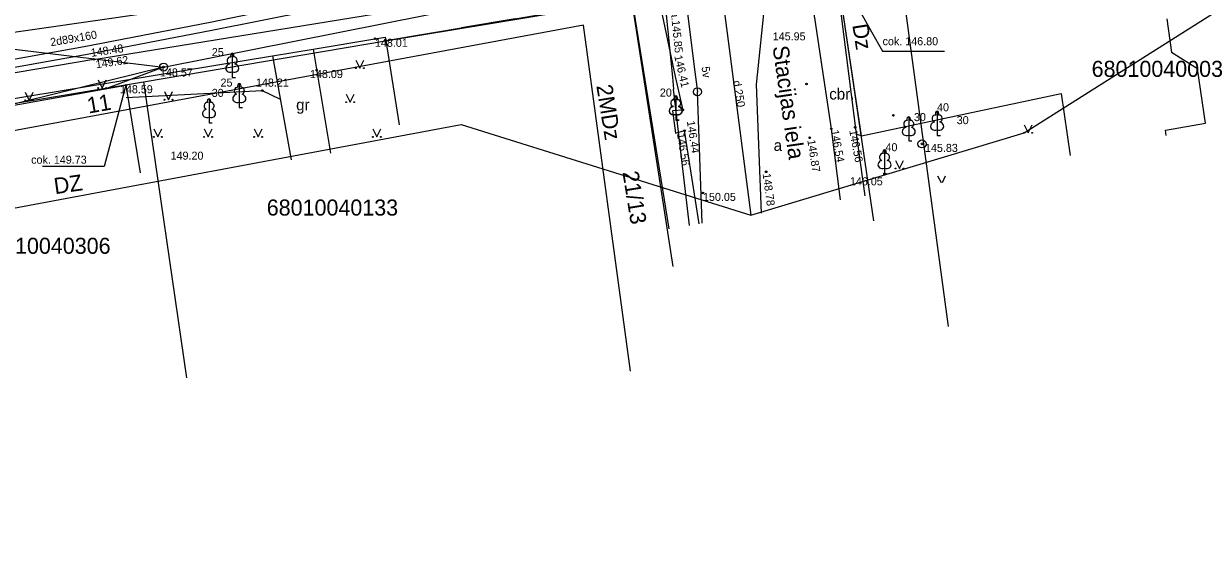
# Model space of a CAD drawing. Extents: x 728492 to 729038, y 272968 to 273171.
# Drawn here: x 728626.4 to 728700.1, y 273032.9 to 273065.2 of the extents above; entities that cross this region are included whole.
import ezdxf

# ---------------------------------------------------------------- set-up
doc = ezdxf.new("R2010")
doc.units = 0
for name, color, linetype in [('APGR_SARK_####_####_#', 7, 'Continuous'), ('BUVE_BDET_####_####_#', 7, 'Continuous'), ('BUVE_BDET_####_TKST_#', 7, 'Continuous'), ('BUVE_EKAS_####_####_#', 7, 'Continuous'), ('BUVE_EKAS_ADRS_TKST_#', 7, 'Continuous'), ('BUVE_EKAS_RAKS_TKST_#', 7, 'Continuous'), ('CELI_CAPM_####_####_#', 7, 'Continuous'), ('CELI_CMAL_####_####_#', 7, 'Continuous'), ('CELI_CSEG_####_TKST_#', 7, 'Continuous'), ('CELI_IELA_####_TKST_#', 7, 'Continuous'), ('CELI_SEGL_####_####_#', 7, 'Continuous'), ('ELEK_ELEM_####_####_#', 7, 'Continuous'), ('ELEK_VADV_ZSPR_####_#', 7, 'Continuous'), ('ELEK_VADV_ZSPR_TKST_#', 7, 'Continuous'), ('NORB_ZOGS_ZSTP_####_#', 7, 'Continuous'), ('RAMI_UZMR_####_####_#', 7, 'Continuous'), ('RELJ_AATZ_####_TKST_#', 7, 'Continuous'), ('RELJ_ELEM_####_####_#', 7, 'Continuous'), ('ROBZ_KADS_####_TKST_#', 7, 'Continuous'), ('ROBZ_UZMR_####_####_#', 7, 'Continuous'), ('SAKK_KKAN_####_####_#', 7, 'Continuous'), ('SAKK_KKAN_####_TKST_#', 7, 'Continuous'), ('SAKT_ELEM_####_####_#', 7, 'Continuous'), ('SAKT_VADV_KLIN_####_#', 7, 'Continuous'), ('SAKT_VADV_PKAB_####_#', 7, 'Continuous'), ('SILT_VADP_UDEN_####_#', 7, 'Continuous'), ('SILT_VADP_UDEN_TKST_#', 7, 'Continuous'), ('SKAN_VADP_PAST_####_#', 7, 'Continuous'), ('SKAN_VADP_PAST_TKST_#', 7, 'Continuous'), ('TERT_DIAM_####_TKST_#', 7, 'Continuous'), ('TERT_ELEM_####_####_#', 7, 'Continuous'), ('UDTK_VADP_UDEN_####_#', 7, 'Continuous')]:
    doc.layers.add(name, color=color, linetype=linetype)

msp = doc.modelspace()

# ---------------------------------------------------------------- linework, layer by layer
at = {"layer": 'APGR_SARK_####_####_#'}
for points in [[(728684.022, 273046.348), (728680.999, 273068.647)], [(728661.295, 273065.109), (728551.197, 273044.726)], [(728664.216, 273043.568), (728661.295, 273065.109)]]:
    msp.add_lwpolyline(points, dxfattribs=at)
at = {"layer": 'BUVE_BDET_####_####_#'}
for points in [[(728677.051, 273068.571), (728679.223, 273064.706)], [(728679.223, 273064.706), (728679.908, 273063.488), (728683.759, 273063.488)], [(728632.791, 273061.372), (728631.436, 273056.307), (728627.592, 273056.307)]]:
    msp.add_lwpolyline(points, dxfattribs=at)
at = {"layer": 'BUVE_EKAS_####_####_#'}
for p, q in [((728678.601, 273058.219), (728677.051, 273068.571)), ((728648.966, 273064.165), (728664.302, 273066.748)), ((728664.302, 273066.748), (728666.605, 273052.429)), ((728653.698, 273064.962), (728657.04, 273065.525)), ((728697.622, 273065.502), (728697.893, 273063.412)), ((728648.966, 273064.165), (728649.808, 273058.918)), ((728699.521, 273062.386), (728697.893, 273063.412)), ((728700.011, 273059.008), (728699.521, 273062.386)), ((728623.429, 273059.709), (728632.791, 273061.372)), ((728632.791, 273061.372), (728633.674, 273055.93)), ((728678.601, 273058.219), (728691.026, 273060.86)), ((728691.026, 273060.86), (728691.595, 273056.997)), ((728697.52, 273058.569), (728700.011, 273059.008)), ((728697.568, 273058.25), (728697.52, 273058.569))]:
    msp.add_line(p, q, dxfattribs=at)
at = {"layer": 'CELI_CAPM_####_####_#'}
msp.add_line((728630.786, 273062.984), (728591.431, 273056.294), dxfattribs=at)
for points in [[(728676.374, 273071.049), (728675.428, 273070.679), (728675.22, 273070.334), (728675.222, 273068.615), (728676.716, 273058.658)], [(728630.786, 273062.984), (728648.342, 273065.816), (728648.342, 273065.816)]]:
    msp.add_lwpolyline(points, dxfattribs=at)
at = {"layer": 'CELI_CMAL_####_####_#'}
for p, q in [((728676.907, 273068.954), (728678.26, 273058.341)), ((728665.881, 273067.196), (728666.991, 273061.921)), ((728644.444, 273063.627), (728648.298, 273064.265)), ((728648.298, 273064.265), (728648.942, 273064.369)), ((728648.942, 273064.369), (728648.966, 273064.165)), ((728644.444, 273063.627), (728645.536, 273057.144)), ((728622.936, 273060.066), (728641.923, 273063.209)), ((728641.923, 273063.209), (728643.073, 273056.729)), ((728666.991, 273061.921), (728667.467, 273059.826)), ((728667.467, 273059.826), (728666.833, 273059.781)), ((728666.833, 273059.781), (728667.014, 273058.397)), ((728667.014, 273058.397), (728667.579, 273058.547)), ((728668.492, 273052.747), (728667.579, 273058.547)), ((728676.716, 273058.658), (728677.279, 273054.231)), ((728678.26, 273058.341), (728678.807, 273054.489))]:
    msp.add_line(p, q, dxfattribs=at)
msp.add_lwpolyline([(728678.26, 273058.341), (728678.601, 273058.219)], dxfattribs=at)
at = {"layer": 'CELI_SEGL_####_####_#'}
msp.add_line((728641.923, 273063.209), (728644.444, 273063.627), dxfattribs=at)
at = {"layer": 'ELEK_ELEM_####_####_#'}
for centre in [(728668.384, 273060.964), (728682.365, 273057.722)]:
    msp.add_circle(centre, 0.25, dxfattribs=at)
at = {"layer": 'ELEK_VADV_ZSPR_####_#'}
for p, q in [((728666.081, 273078.979), (728668.226, 273062.202)), ((728668.226, 273062.202), (728668.384, 273060.964))]:
    msp.add_line(p, q, dxfattribs=at)
msp.add_lwpolyline([(728668.684, 273052.78), (728668.384, 273060.964)], dxfattribs=at)
at = {"layer": 'NORB_ZOGS_ZSTP_####_#'}
msp.add_lwpolyline([(728632.806, 273060.614), (728641.281, 273061.042), (728642.404, 273060.498)], dxfattribs=at)
at = {"layer": 'RAMI_UZMR_####_####_#'}
msp.add_lwpolyline([(728545.121, 273067.256), (728525.538, 273066.106), (728511.145, 273059.016), (728527.731, 273033.328), (728550.271, 273033.197), (728572.013, 273034.886), (728580.562, 273045.27), (728653.673, 273058.931), (728671.713, 273053.291), (728688.721, 273058.407), (728702.149, 273066.922)], dxfattribs=at)
at = {"layer": 'RELJ_ELEM_####_####_#'}
for centre in [(728648.298, 273064.265), (728648.966, 273064.165), (728630.786, 273062.984), (728635.134, 273062.502), (728644.664, 273062.32), (728632.791, 273061.372), (728675.172, 273061.452), (728641.281, 273061.042), (728667.467, 273059.826), (728667.467, 273059.826), (728680.584, 273059.504), (728667.579, 273058.547), (728676.716, 273058.658), (728678.202, 273058.754), (728675.364, 273058.103), (728682.365, 273057.722), (728672.66, 273055.986), (728680.031, 273055.855), (728668.728, 273054.671)]:
    msp.add_circle(centre, 0.05, dxfattribs=at)
at = {"layer": 'ROBZ_UZMR_####_####_#'}
for p, q in [((728677.033, 273068.656), (728679.337, 273052.938)), ((728648.952, 273064.144), (728664.304, 273066.697)), ((728666.873, 273050.088), (728664.304, 273066.697)), ((728633.894, 273061.592), (728648.952, 273064.144)), ((728616.498, 273058.682), (728633.894, 273061.592)), ((728633.894, 273061.592), (728636.566, 273043.16))]:
    msp.add_line(p, q, dxfattribs=at)
at = {"layer": 'SAKK_KKAN_####_####_#'}
for points in [[(728664.534, 273084.574), (728664.542, 273084.535), (728666.095, 273069.085), (728666.099, 273069.049), (728666.82, 273061.882)], [(728666.82, 273061.882), (728666.895, 273061.137)], [(728667.884, 273052.645), (728666.895, 273061.137)]]:
    msp.add_lwpolyline(points, dxfattribs=at)
at = {"layer": 'SAKT_ELEM_####_####_#'}
msp.add_circle((728635.134, 273062.502), 0.25, dxfattribs=at)
at = {"layer": 'SAKT_VADV_KLIN_####_#'}
msp.add_line((728578.857, 273069.237), (728635.134, 273062.502), dxfattribs=at)
msp.add_lwpolyline([(728635.134, 273062.502), (728616.023, 273057.783)], dxfattribs=at)
at = {"layer": 'SAKT_VADV_PKAB_####_#'}
for q in [(728677.472, 273070.914), (728631.476, 273061.138)]:
    msp.add_line((728635.134, 273062.502), q, dxfattribs=at)
at = {"layer": 'SILT_VADP_UDEN_####_#'}
for points in [[(728554.662, 273032.952), (728554.113, 273035.473), (728554.267, 273035.774), (728581.419, 273054.878), (728582.018, 273055.208), (728610.89, 273060.328), (728630.183, 273063.782), (728638.039, 273065.289), (728652.893, 273068.386), (728653.925, 273076.859), (728654.802, 273077.089)], [(728555.193, 273032.922), (728554.64, 273035.405), (728554.656, 273035.436), (728581.684, 273054.453), (728582.187, 273054.73), (728610.978, 273059.835), (728630.274, 273063.29), (728638.144, 273064.8), (728653.493, 273067.873), (728654.384, 273076.462), (728654.897, 273076.597)]]:
    msp.add_lwpolyline(points, dxfattribs=at)
at = {"layer": 'SKAN_VADP_PAST_####_#'}
for p, q in [((728669.124, 273072.987), (728670.474, 273062.714)), ((728670.474, 273062.714), (728671.713, 273053.291))]:
    msp.add_line(p, q, dxfattribs=at)
at = {"layer": 'TERT_ELEM_####_####_#'}
for p, q in [((728647.112, 273062.937), (728647.362, 273062.437)), ((728647.362, 273062.437), (728647.612, 273062.937)), ((728639.409, 273062.21), (728639.409, 273061.863)), ((728631.067, 273061.7), (728631.317, 273061.2)), ((728631.317, 273061.2), (728631.567, 273061.7)), ((728639.409, 273061.863), (728639.609, 273061.863)), ((728626.509, 273060.933), (728626.759, 273060.433)), ((728626.759, 273060.433), (728627.009, 273060.933)), ((728635.188, 273060.973), (728635.438, 273060.473)), ((728635.438, 273060.473), (728635.688, 273060.973)), ((728646.509, 273060.822), (728646.759, 273060.322)), ((728646.759, 273060.322), (728647.009, 273060.822)), ((728639.852, 273060.325), (728639.852, 273059.978)), ((728639.852, 273059.978), (728640.052, 273059.978)), ((728637.965, 273059.38), (728637.965, 273059.033)), ((728667.027, 273059.551), (728667.027, 273059.204)), ((728667.027, 273059.551), (728667.027, 273059.204)), ((728667.027, 273059.204), (728667.227, 273059.204)), ((728667.027, 273059.204), (728667.227, 273059.204)), ((728667.034, 273059.565), (728667.034, 273059.218)), ((728667.034, 273059.218), (728667.234, 273059.218)), ((728634.534, 273058.656), (728634.784, 273058.156)), ((728634.784, 273058.156), (728635.034, 273058.656)), ((728637.653, 273058.656), (728637.903, 273058.156)), ((728637.903, 273058.156), (728638.153, 273058.656)), ((728637.965, 273059.033), (728638.165, 273059.033)), ((728640.773, 273058.656), (728641.023, 273058.156)), ((728641.023, 273058.156), (728641.273, 273058.656)), ((728648.169, 273058.656), (728648.419, 273058.156)), ((728648.419, 273058.156), (728648.669, 273058.656)), ((728683.309, 273058.598), (728683.309, 273058.251)), ((728688.721, 273058.908), (728688.971, 273058.408)), ((728688.971, 273058.408), (728689.221, 273058.908)), ((728681.535, 273058.261), (728681.535, 273057.914)), ((728681.535, 273057.914), (728681.735, 273057.914)), ((728683.309, 273058.251), (728683.509, 273058.251)), ((728680.031, 273056.202), (728680.031, 273055.855)), ((728680.721, 273056.692), (728680.971, 273056.192)), ((728680.971, 273056.192), (728681.221, 273056.692)), ((728680.031, 273055.855), (728680.231, 273055.855)), ((728683.338, 273055.735), (728683.55, 273055.31)), ((728683.634, 273055.328), (728683.838, 273055.735))]:
    msp.add_line(p, q, dxfattribs=at)
for points in [[(728639.409, 273063.363), (728639.409, 273062.21)], [(728639.499, 273063.131), (728639.498, 273063.132)], [(728639.852, 273061.478), (728639.852, 273060.325)], [(728639.942, 273061.246), (728639.941, 273061.247)], [(728667.027, 273060.704), (728667.027, 273059.551)], [(728667.027, 273060.704), (728667.027, 273059.551)], [(728667.034, 273060.718), (728667.034, 273059.565)], [(728637.965, 273060.533), (728637.965, 273059.38)], [(728638.055, 273060.301), (728638.054, 273060.302)], [(728667.117, 273060.472), (728667.116, 273060.473)], [(728667.117, 273060.472), (728667.116, 273060.473)], [(728667.124, 273060.486), (728667.123, 273060.487)], [(728681.535, 273059.414), (728681.535, 273058.261)], [(728681.625, 273059.181), (728681.624, 273059.182)], [(728683.309, 273059.751), (728683.309, 273058.598)], [(728683.399, 273059.519), (728683.398, 273059.52)], [(728680.031, 273057.355), (728680.031, 273056.202)], [(728680.121, 273057.123), (728680.12, 273057.124)]]:
    msp.add_lwpolyline(points, dxfattribs=at)
for centre, radius in [((728647.112, 273062.436), 0.028), ((728647.612, 273062.436), 0.0263), ((728631.067, 273061.199), 0.028), ((728631.567, 273061.199), 0.0263), ((728626.508, 273060.433), 0.028), ((728627.008, 273060.433), 0.0263), ((728635.188, 273060.472), 0.028), ((728635.688, 273060.472), 0.0263), ((728646.508, 273060.321), 0.028), ((728647.008, 273060.321), 0.0263), ((728688.721, 273058.407), 0.028), ((728689.221, 273058.407), 0.0263), ((728634.534, 273058.155), 0.028), ((728635.034, 273058.155), 0.0263), ((728637.653, 273058.155), 0.028), ((728638.153, 273058.155), 0.0263), ((728640.773, 273058.155), 0.028), ((728641.273, 273058.155), 0.0263), ((728648.169, 273058.155), 0.028), ((728648.669, 273058.155), 0.0263), ((728680.721, 273056.191), 0.028), ((728681.221, 273056.191), 0.0263)]:
    msp.add_circle(centre, radius, dxfattribs=at)
for centre, major_axis, ratio, start_param, end_param in [((728639.281, 273062.918), (-0.039, -0.212), 0.861323, 3.141593, 6.283185), ((728639.409, 273063.213), (0, -0.15), 0.707107, 3.14537, 5.287485), ((728639.409, 273063.213), (0, -0.15), 0.707107, 0.995701, 3.137816), ((728639.537, 273062.918), (0.039, -0.212), 0.861323, 0, 3.141593), ((728639.319, 273062.456), (0.307, 0.095), 0.814445, 1.570796, 4.752015), ((728639.499, 273062.456), (-0.307, 0.095), 0.814445, 1.531171, 4.712389), ((728639.852, 273061.328), (0, -0.15), 0.707107, 3.14537, 5.287485), ((728639.852, 273061.328), (0, -0.15), 0.707107, 0.995701, 3.137816), ((728639.762, 273060.571), (0.307, 0.095), 0.814445, 1.570796, 4.752015), ((728639.724, 273061.033), (-0.039, -0.212), 0.861323, 3.141593, 6.283185), ((728639.942, 273060.571), (-0.307, 0.095), 0.814445, 1.531171, 4.712389), ((728639.98, 273061.033), (0.039, -0.212), 0.861323, 0, 3.141593), ((728667.027, 273060.554), (0, -0.15), 0.707107, 3.14537, 5.287485), ((728667.027, 273060.554), (0, -0.15), 0.707107, 3.14537, 5.287485), ((728667.035, 273060.568), (0, -0.15), 0.707107, 3.14537, 5.287485), ((728667.027, 273060.554), (0, -0.15), 0.707107, 0.995701, 3.137816), ((728667.027, 273060.554), (0, -0.15), 0.707107, 0.995701, 3.137816), ((728667.034, 273060.568), (0, -0.15), 0.707107, 0.995701, 3.137816), ((728637.875, 273059.626), (0.307, 0.095), 0.814445, 1.570796, 4.752015), ((728637.837, 273060.088), (-0.039, -0.212), 0.861323, 3.141593, 6.283185), ((728637.965, 273060.383), (0, -0.15), 0.707107, 3.14537, 5.287485), ((728637.965, 273060.383), (0, -0.15), 0.707107, 0.995701, 3.137816), ((728638.055, 273059.626), (-0.307, 0.095), 0.814445, 1.531171, 4.712389), ((728638.093, 273060.088), (0.039, -0.212), 0.861323, 0, 3.141593), ((728666.937, 273059.797), (0.307, 0.095), 0.814445, 1.570796, 4.752015), ((728666.937, 273059.797), (0.307, 0.095), 0.814445, 1.570796, 4.752015), ((728666.945, 273059.811), (0.307, 0.095), 0.814445, 1.570796, 4.752015), ((728666.899, 273060.259), (-0.039, -0.212), 0.861323, 3.141593, 6.283185), ((728666.899, 273060.259), (-0.039, -0.212), 0.861323, 3.141593, 6.283185), ((728666.906, 273060.273), (-0.039, -0.212), 0.861323, 3.141593, 6.283185), ((728667.117, 273059.797), (-0.307, 0.095), 0.814445, 1.531171, 4.712389), ((728667.117, 273059.797), (-0.307, 0.095), 0.814445, 1.531171, 4.712389), ((728667.124, 273059.811), (-0.307, 0.095), 0.814445, 1.531171, 4.712389), ((728667.155, 273060.259), (0.039, -0.212), 0.861323, 0, 3.141593), ((728667.155, 273060.259), (0.039, -0.212), 0.861323, 0, 3.141593), ((728667.163, 273060.273), (0.039, -0.212), 0.861323, 0, 3.141593), ((728681.407, 273058.969), (-0.039, -0.212), 0.861323, 3.141593, 6.283185), ((728681.536, 273059.264), (0, -0.15), 0.707107, 3.14537, 5.287485), ((728681.535, 273059.264), (0, -0.15), 0.707107, 0.995701, 3.137816), ((728681.664, 273058.969), (0.039, -0.212), 0.861323, 0, 3.141593), ((728683.219, 273058.844), (0.307, 0.095), 0.814445, 1.570796, 4.752015), ((728683.181, 273059.306), (-0.039, -0.212), 0.861323, 3.141593, 6.283185), ((728683.309, 273059.601), (0, -0.15), 0.707107, 3.14537, 5.287485), ((728683.309, 273059.601), (0, -0.15), 0.707107, 0.995701, 3.137816), ((728683.399, 273058.844), (-0.307, 0.095), 0.814445, 1.531171, 4.712389), ((728683.437, 273059.306), (0.039, -0.212), 0.861323, 0, 3.141593), ((728681.446, 273058.507), (0.307, 0.095), 0.814445, 1.570796, 4.752015), ((728681.625, 273058.507), (-0.307, 0.095), 0.814445, 1.531171, 4.712389), ((728679.903, 273056.91), (-0.039, -0.212), 0.861323, 3.141593, 6.283185), ((728680.031, 273057.205), (0, -0.15), 0.707107, 3.14537, 5.287485), ((728680.031, 273057.205), (0, -0.15), 0.707107, 0.995701, 3.137816), ((728680.159, 273056.91), (0.039, -0.212), 0.861323, 0, 3.141593), ((728679.941, 273056.448), (0.307, 0.095), 0.814445, 1.570796, 4.752015), ((728680.121, 273056.448), (-0.307, 0.095), 0.814445, 1.531171, 4.712389)]:
    msp.add_ellipse(centre, major_axis=major_axis, ratio=ratio, start_param=start_param, end_param=end_param, dxfattribs=at)
at = {"layer": 'UDTK_VADP_UDEN_####_#'}
msp.add_line((728672.055, 273061.416), (728673.218, 273072.807), dxfattribs=at)
for points in [[(728536.753, 273051.73), (728562.041, 273055.954), (728585.763, 273058.374), (728605.397, 273061.619), (728606.945, 273061.767), (728607.469, 273061.897), (728613.688, 273063.022), (728614.11, 273063.005), (728657.437, 273069.243)], [(728672.363, 273053.401), (728672.055, 273061.416)]]:
    msp.add_lwpolyline(points, dxfattribs=at)

# ---------------------------------------------------------------- texts
at = {"layer": 'BUVE_BDET_####_TKST_#'}
for s, p in [('cok. 146.80', (728679.911, 273063.862)), ('cok. 149.73', (728626.889, 273056.488))]:
    msp.add_text(s, height=0.49999, dxfattribs=at).set_placement(p)
at = {"layer": 'BUVE_EKAS_ADRS_TKST_#'}
for s, rotation, p in [('11', 10.019, (728630.465, 273059.606)), ('21/13', 279.16114, (728663.709, 273055.959))]:
    msp.add_text(s, height=1, rotation=rotation, dxfattribs=at).set_placement(p)
at = {"layer": 'BUVE_EKAS_RAKS_TKST_#'}
for s, rotation, p in [('Dz', 278.953, (728678.022, 273065.124)), ('2MDz', 279.16114, (728662.081, 273061.338)), ('DZ', 8.101, (728628.377, 273054.59))]:
    msp.add_text(s, height=1, rotation=rotation, dxfattribs=at).set_placement(p)
at = {"layer": 'CELI_CSEG_####_TKST_#'}
for s, p in [('cbr.', (728676.592, 273060.48)), ('gr', (728643.391, 273059.808)), ('a', (728673.128, 273057.286))]:
    msp.add_text(s, height=0.7, dxfattribs=at).set_placement(p)
at = {"layer": 'CELI_IELA_####_TKST_#'}
msp.add_text('Stacijas iela', height=1, rotation=278.23269, dxfattribs=at).set_placement((728673.056, 273063.768))
at = {"layer": 'ELEK_VADV_ZSPR_TKST_#'}
msp.add_text('5v', height=0.5, rotation=277.284, dxfattribs=at).set_placement((728668.637, 273062.512))
at = {"layer": 'RELJ_AATZ_####_TKST_#'}
for s, p in [('148.01', (728648.298, 273063.765)), (' 145.95', (728672.885, 273064.167)), (' 148.57', (728634.722, 273061.919)), (' 148.09', (728644.068, 273061.82)), (' 148.59', (728632.231, 273060.875)), (' 148.21', (728640.701, 273061.289)), (' 145.83', (728682.365, 273057.222)), (' 149.20', (728635.386, 273056.739)), (' 146.05', (728677.689, 273055.142)), ('150.05', (728668.728, 273054.171))]:
    msp.add_text(s, height=0.5, dxfattribs=at).set_placement(p)
for s, rotation, p in [('148.48', 8.46816, (728630.643, 273063.138)), ('149.62', 8.17512, (728630.947, 273062.425)), (' 146.41', 283.01472, (728666.891, 273063.365)), (' 146.44', 278.77823, (728667.69, 273059.311)), (' 146.56', 278.77823, (728667.076, 273058.538)), ('146.54', 280.56501, (728676.68, 273058.551)), ('146.56', 280.56501, (728677.833, 273058.551)), ('146.87', 279.23863, (728675.22, 273057.947)), ('148.78', 277.67271, (728672.439, 273055.862))]:
    msp.add_text(s, height=0.5, rotation=rotation, dxfattribs=at).set_placement(p)
at = {"layer": 'ROBZ_KADS_####_TKST_#'}
for s, p in [('68010040003', (728692.929, 273061.893)), ('68010040133', (728641.56, 273053.26)), ('68010040306', (728623.653, 273050.881))]:
    msp.add_text(s, height=1, dxfattribs=at).set_placement(p)
at = {"layer": 'SAKK_KKAN_####_TKST_#'}
msp.add_text('c.a.145.85', height=0.5, rotation=275.74895, dxfattribs=at).set_placement((728666.668, 273066.47))
at = {"layer": 'SILT_VADP_UDEN_TKST_#'}
msp.add_text('2d89x160', height=0.5, rotation=9.762, dxfattribs=at).set_placement((728628.124, 273063.797))
at = {"layer": 'SKAN_VADP_PAST_TKST_#'}
msp.add_text('d.250', height=0.5, rotation=280.16492, dxfattribs=at).set_placement((728670.583, 273061.618))
at = {"layer": 'TERT_DIAM_####_TKST_#'}
for s, p in [('25', (728638.14, 273063.188)), ('25', (728638.682, 273061.288)), ('30', (728638.134, 273060.648)), ('20', (728666.042, 273060.667)), ('40', (728683.302, 273059.753)), ('30', (728681.863, 273059.138)), ('30', (728684.528, 273058.951)), ('40', (728680.09, 273057.264))]:
    msp.add_text(s, height=0.5, dxfattribs=at).set_placement(p)

doc.saveas('drawing.dxf')
